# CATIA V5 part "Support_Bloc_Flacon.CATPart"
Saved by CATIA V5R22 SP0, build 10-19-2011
Part number: Support_Bloc_Flacon
Bounding box of the stored display mesh (mm): x -215 to 215, y -45 to 45, z 0 to 5
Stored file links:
  D:\PER\CAO_PER_MODIF_2025\CAO_PER_pick&place_2024P\Sous_Ensemble_Flacon\Support_Bloc_Flacon.CATPart
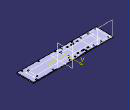
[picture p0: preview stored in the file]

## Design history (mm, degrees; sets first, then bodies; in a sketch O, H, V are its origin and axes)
Body1 (main body)
  Sketch1 on xy-plane, origin (0, 0, 0), H (1, 0, 0), V (0, 1, 0)
    point P1 (-215, 45)
    line L1 (-215, 45) -> (215, 45)
    line L2 (215, 45) -> (215, -45)
    line L3 (215, -45) -> (-215, -45)
    line L4 (-215, -45) -> (-215, 45)
    point P2 (215, 45)
    point P3 (215, -45)
    point P4 (-215, -45)
    length L4 = 90
    length L1 = 430
    horizontal: L1 H, L3 H
    vertical: L2 V, L4 V
    equidistance: P3 P1 O, P2 P4 O
  Pad1: profile Sketch1, direction (0, 0, 1), length 5
  Sketch2 on end face of Pad1, origin (0, 0, 5), H (1, 0, 0), V (0, 1, 0)
    point P1 (-157.5, 0)
    line L1 (-110, 35.25) -> (-110, -35.25)
    line L2 (-110, -35.25) -> (-205, -35.25)
    line L3 (-205, -35.25) -> (-205, 35.25)
    line L4 (-205, 35.25) -> (-110, 35.25)
    reference projected line E1 (-215, 45) -> (-215, -45) from edge [face of Pad1 from Sketch1.L4 | end face of Pad1]
    line L5 (-157.5, 35.25) -> (-157.5, -35.25)
    point P6 (-157.5, 35.25)
    point P7 (-157.5, -35.25)
    distance L4 L2 = 70.5
    distance L3 E1 = 10
    distance L3 L5 = 47.5
    coincidence: P1 H
    vertical: L1 V, L3 V, L5 V
    horizontal: L2 H, L4 H
    equidistance: L1 L3 P1, L2 L4 P1
    midpoint: P6 L4, P7 L2
  DatumCurve1
  Sketch3 on end face of Pad1, origin (0, 0, 5), H (1, 0, 0), V (0, 1, 0)
    circle A1 centre (-199.906, -35.25) radius 3.25
    point P1 (-199.906, -35.25)
    circle A2 centre (-159.906, -35.25) radius 3.25
    point P2 (-159.906, -35.25)
    circle A3 centre (-119.906, -35.25) radius 3.25
    point P3 (-119.906, -35.25)
    reference projected line E1 (-215, 45) -> (-215, -45) from edge [face of Pad1 from Sketch1.L4 | end face of Pad1]
    radius A3 = 3.25
    radius A2 = 3.25
    radius A1 = 3.25
    distance P2 P1 = 40
    distance P3 P2 = 40
    distance E1 P1 = 15.094
  Pocket1: profile Sketch3, direction (0, 0, -1), through (limit type 3)
  Chamfer1: length 4, angle 45, on edge [face of Pocket1 from Sketch3.A1 | start face of Pad1]; edge [face of Pocket1 from Sketch3.A2 | start face of Pad1]; edge [face of Pocket1 from Sketch3.A3 | start face of Pad1]
  Mirror1: of Pocket1, Chamfer1, about zx-plane
  Sketch4 on end face of Pad1, origin (0, 0, 5), H (1, 0, 0), V (0, 1, 0)
    point P1 (0, -19)
    line L1 (0, -19) -> (190, -19)
    line L2 (190, -19) -> (190, 19)
    line L3 (190, 19) -> (0, 19)
    line L4 (0, 19) -> (0, -19)
    point P2 (190, -19)
    point P3 (190, 19)
    point P4 (0, 19)
    line L5 (0, -19) -> (-170, -19)
    line L6 (-170, -19) -> (-170, 19)
    line L7 (-170, 19) -> (0, 19)
    line L8 (0, 19) -> (0, -19)
    point P6 (-170, 19)
    distance P4 P3 = 190
    distance P3 P2 = 38
    distance L8 L6 = 170
    coincidence: P1 V, P6 L3
    horizontal: L1 H, L3 H, L5 H, L7 H
    vertical: L2 V, L4 V, L6 V, L8 V
    symmetry: L3 L1 H
  Sketch5 on end face of Pad1, origin (0, 0, 5), H (1, 0, 0), V (0, 1, 0)
    point P1 (-141, 0)
    point P2 (-76, 26)
    line L1 (-76, 26) -> (-60, 26)
    line L2 (-60, 26) -> (-60, 31.2)
    line L3 (-60, 31.2) -> (-76, 31.2)
    line L4 (-76, 31.2) -> (-76, 26)
    point P3 (-60, 26)
    point P4 (-60, 31.2)
    point P5 (-76, 31.2)
    point P6 (-91, 26)
    line L5 (-91, 26) -> (-99, 26)
    line L6 (-99, 26) -> (-99, 31.2)
    line L7 (-99, 31.2) -> (-91, 31.2)
    line L8 (-91, 31.2) -> (-91, 26)
    point P7 (-99, 26)
    point P8 (-99, 31.2)
    point P9 (-91, 31.2)
    point P10 (-45, 31.2)
    line L9 (-45, 31.2) -> (-37, 31.2)
    line L10 (-37, 31.2) -> (-37, 26)
    line L11 (-37, 26) -> (-45, 26)
    line L12 (-45, 26) -> (-45, 31.2)
    point P11 (-37, 31.2)
    point P12 (-37, 26)
    point P13 (-45, 26)
    point P14 (-76, -26)
    point P15 (-60, -26)
    point P16 (-60, -31.2)
    point P17 (-76, -31.2)
    point P18 (-91, -26)
    point P19 (-99, -26)
    point P20 (-99, -31.2)
    point P21 (-91, -31.2)
    point P22 (-45, -31.2)
    point P23 (-37, -31.2)
    point P24 (-37, -26)
    point P25 (-45, -26)
    line L13 (-76, -26) -> (-60, -26)
    line L14 (-60, -26) -> (-60, -31.2)
    line L15 (-60, -31.2) -> (-76, -31.2)
    line L16 (-76, -31.2) -> (-76, -26)
    line L17 (-91, -26) -> (-99, -26)
    line L18 (-99, -26) -> (-99, -31.2)
    line L19 (-99, -31.2) -> (-91, -31.2)
    line L20 (-91, -31.2) -> (-91, -26)
    line L21 (-45, -31.2) -> (-37, -31.2)
    line L22 (-37, -31.2) -> (-37, -26)
    line L23 (-37, -26) -> (-45, -26)
    line L24 (-45, -26) -> (-45, -31.2)
    reference projected point E1 (-110, 35.25) from vertex [element of Sketch2 | element of Sketch2]
    distance P5 P4 = 16
    distance P4 P3 = 5.2
    distance L1 H = 26
    distance P8 P9 = 8
    distance L8 L4 = 15
    distance P10 P11 = 8
    distance L12 L2 = 15
    distance L6 E1 = 11
    horizontal: L1 H, L3 H, L5 H, L7 H, L9 H, L11 H
    vertical: L2 V, L4 V, L6 V, L8 V, L10 V, L12 V
    coincidence: P6 L1, P8 L3, P10 L3, P12 L1
    symmetry: P2 P14 H, P3 P15 H, P4 P16 H, P5 P17 H, P6 P18 H, P7 P19 H, P8 P20 H, P9 P21 H, P10 P22 H, P11 P23 H, P12 P24 H, P13 P25 H, L1 L13 H, L2 L14 H, L3 L15 H, L4 L16 H, L5 L17 H, L6 L18 H, L7 L19 H, L8 L20 H, L9 L21 H, L10 L22 H, L11 L23 H, L12 L24 H
  Pocket2: profile Sketch5, direction (0, 0, -1), through (limit type 6)
  Sketch6 on end face of Pad1, origin (0, 0, 5), H (1, 0, 0), V (0, 1, 0)
    line L1 (175, -23.5) -> (175, 23.5)
    point P1 (175, -23.5)
    point P2 (175, 23.5)
    reference projected line E1 (-37, 26) -> (-37, 31.2) from edge [end face of Pad1 | face of Pocket2 from Sketch5.L10]
    distance P2 P1 = 47
    distance L1 E1 = 212
    vertical: L1 V
    symmetry: P1 P2 H
  Sketch7 on end face of Pad1, origin (0, 0, 5), H (1, 0, 0), V (0, 1, 0)
    circle A1 centre (175, 23.5) radius 2.5
    point P1 (175, 23.5)
    reference projected point E1 (175, 23.5) from Sketch6.P2
    circle A2 centre (175, -23.5) radius 2.5
    point P2 (175, -23.5)
    reference projected point E2 (175, -23.5) from Sketch6.P1
    radius A1 = 2.5
    radius A2 = 2.5
    coincidence: P1 E1, P2 E2
  Pocket3: profile Sketch7, direction (0, 0, -1), through (limit type 6)
  Chamfer2: length 3, angle 45, on edge [face of Pocket3 from Sketch7.A2 | start face of Pad1]; edge [face of Pocket3 from Sketch7.A1 | start face of Pad1]
  RectPattern1: of Pocket3, Chamfer2, direction 1 instances 2, spacing 171, along edge [face of Pad1 from Sketch1.L1 | end face of Pad1], direction 2 instances 2, spacing 38
  DatumCurve2 to DatumCurve4
  Sketch8 on end face of Pad1, origin (0, 0, 5), H (1, 0, 0), V (0, 1, 0)
    circle A1 centre (-18.6436, -36.5) radius 3.25
    reference projected circle E1 centre (-18.6436, -36.5) radius 3.5 from edge of DatumCurve3
    circle A2 centre (-18.6436, 36.5) radius 3.25
    reference projected circle E2 centre (-18.6436, 36.5) radius 3.5 from edge of DatumCurve4
    radius A1 = 3.25
    radius A2 = 3.25
    concentricity: A1 E1, A2 E2
  Pocket4: profile Sketch8, direction (0, 0, -1), through (limit type 3)
  Chamfer3: length 4, angle 45, on edge [face of Pocket4 from Sketch8.A1 | start face of Pad1]; edge [face of Pocket4 from Sketch8.A2 | start face of Pad1]
  Sketch9 on end face of Pad1, origin (193.4263, -31.8247, 5), H (1, 0, 0), V (0, 1, 0)
    point P1 (0, -7.1753)
    reference projected line E1 (-408.4263, -13.1753) -> (21.5737, -13.1753) from edge [face of Pad1 from Sketch1.L3 | end face of Pad1]
    axis line L1 (88.068, 31.8247) -> (-138.8731, 31.8247)
    reference projected line E2 (21.5737, 76.8247) -> (-408.4263, 76.8247) from edge [face of Pad1 from Sketch1.L1 | end face of Pad1]
    reference projected line E3 (-408.4263, -13.1753) -> (21.5737, -13.1753) from edge [face of Pad1 from Sketch1.L3 | end face of Pad1]
    point P4 (-93.1378, -7.1753)
    point P5 (-186.2756, -7.1753)
    point P6 (-279.4135, -7.1753)
    point P7 (0, 70.8247)
    point P8 (-93.1378, 70.8247)
    point P9 (-279.4135, 70.8247)
    distance P1 E1 = 6
    horizontal: L1 H
    symmetry: E2 E3 L1, P1 P7 L1, P4 P8 L1, P6 P9 L1
  Hole1: placed by Sketch9, at (193.4263, -39, 5) direction (0, 0, -1), diameter 7, through (limit type 3)
  RectPattern2: of Hole1, direction 1 instances 4, spacing 90, along edge [face of Pad1 from Sketch1.L3 | end face of Pad1] reversed
  Plane1: type Offset, RefPlane face of Pad1 from Sketch1.L1, Offset 45
  Mirror2: of Hole1, about Plane1
  RectPattern3: of RectPattern2, direction 1 instances 1, spacing 90, direction 2 instances 2, spacing 78, along edge [face of Pad1 from Sketch1.L2 | end face of Pad1]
